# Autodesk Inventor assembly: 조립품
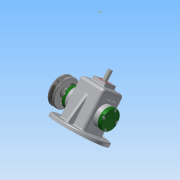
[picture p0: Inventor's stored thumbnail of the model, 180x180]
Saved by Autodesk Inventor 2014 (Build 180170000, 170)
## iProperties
Created: 2017-07
Part Number: 조립품
Document SubType Name: Assembly
Designer: 406-12
Author: 406-12
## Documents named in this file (16)
- C:\Users\406-12\Desktop\470707V1023 김민기\조립품.iam
- C:\Users\406-12\Desktop\470707V1023 김민기\본체.ipt
- C:\Users\406-12\Desktop\470707V1023 김민기\V벨트풀리.ipt
- C:\Users\406-12\Desktop\470707V1023 김민기\고정핀 1.2 x  8.ipt
- C:\Users\406-12\Desktop\470707V1023 김민기\뒤커버.ipt
- C:\Users\406-12\Desktop\470707V1023 김민기\링크.ipt
- C:\Users\406-12\Desktop\470707V1023 김민기\멈춤나사 M3x8.ipt
- C:\Users\406-12\Desktop\470707V1023 김민기\베어링 12 x 32 x 10.ipt
- C:\Users\406-12\Desktop\470707V1023 김민기\볼트 M4 x 12.ipt
- C:\Users\406-12\Desktop\470707V1023 김민기\부시.ipt
- C:\Users\406-12\Desktop\470707V1023 김민기\슬라이드.ipt
- C:\Users\406-12\Desktop\470707V1023 김민기\앞커버.ipt
- C:\Users\406-12\Desktop\470707V1023 김민기\오일실 12 25 7.ipt
- C:\Users\406-12\Desktop\470707V1023 김민기\키 4 x 4 x 10.ipt
- C:\Users\406-12\Desktop\470707V1023 김민기\편심축.ipt
- C:\Users\406-12\Desktop\470707V1023 김민기\핀 5 x 18.ipt
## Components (3 placed, 3 different names)
1. V벨트풀리:1
2. 고정핀 1.2 x  8:1
3. 핀 5 x 18:1
